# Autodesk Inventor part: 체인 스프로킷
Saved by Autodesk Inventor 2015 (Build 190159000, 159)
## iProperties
Created: 2026-07
Part Number: 체인 스프로킷
Material: 일반
Document SubType Name: Modeling
Designer: user
Density: 1 g/cm^3
Appearance: 기본값
Author: user
Author: jhkim
Creation Date: 2026-07-01
Sending System: Autodesk Inventor 2027
Preprocessor: ST-DEVELOPER v20.1
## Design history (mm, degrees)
node "체인 스프로킷1"
body "Solid1"
node "기준1"
